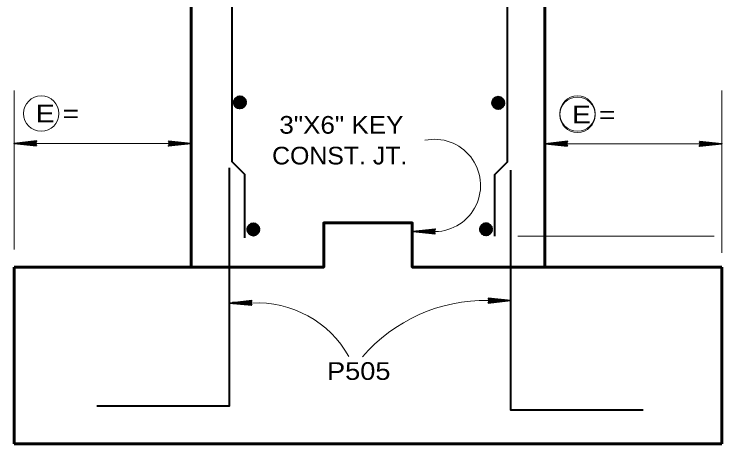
# Model space of a CAD drawing. Extents: x 14.14 to 17.34, y -1.61 to 0.38.
# Drawn here: x 15.5046 to 15.8379, y -1.286 to -1.0834 of the extents above; entities that cross this region are included whole.
import ezdxf

# ---------------------------------------------------------------- set-up
doc = ezdxf.new("R2010")
doc.units = 0
doc.header["$LTSCALE"] = 0.0033
doc.layers.add('1', color=7, linetype='Continuous', lineweight=40)

msp = doc.modelspace()

# ---------------------------------------------------------------- linework, layer by layer
at = {"layer": '1', "lineweight": 13}
for p, q in [((15.504583, -1.194417), (15.504583, -1.119333)), ((15.837917, -1.195917), (15.837917, -1.119333)), ((15.504583, -1.144333), (15.586, -1.144333)), ((15.756167, -1.1445), (15.837917, -1.1445)), ((15.741833, -1.188), (15.83425, -1.188)), ((15.7905, -1.286), (15.8325, -1.286))]:
    msp.add_line(p, q, dxfattribs=at)
at = {"layer": '1'}
for p, q in [((15.60925, -1.123083), (15.613083, -1.12375)), ((15.611167, -1.123917), (15.6125, -1.122917)), ((15.61325, -1.12375), (15.612, -1.122583)), ((15.730917, -1.123333), (15.73475, -1.124)), ((15.732833, -1.124167), (15.734167, -1.123167)), ((15.734917, -1.124), (15.733667, -1.122833)), ((15.608667, -1.126167), (15.6125, -1.126917)), ((15.608667, -1.126333), (15.6125, -1.127083)), ((15.60875, -1.125667), (15.612667, -1.126417)), ((15.60875, -1.125833), (15.612583, -1.126583)), ((15.60875, -1.126083), (15.612583, -1.12675)), ((15.608833, -1.123417), (15.613417, -1.125583)), ((15.608833, -1.12525), (15.61275, -1.126)), ((15.608917, -1.124833), (15.61275, -1.125583)), ((15.608917, -1.125), (15.61275, -1.12575)), ((15.609, -1.124417), (15.612833, -1.125083)), ((15.609, -1.124583), (15.612833, -1.125333)), ((15.609083, -1.123833), (15.613, -1.124583)), ((15.609083, -1.124), (15.613, -1.12475)), ((15.609083, -1.12425), (15.612917, -1.125)), ((15.609167, -1.123417), (15.613083, -1.124083)), ((15.609167, -1.123583), (15.613083, -1.124333)), ((15.613, -1.126583), (15.60925, -1.127)), ((15.730333, -1.126417), (15.734167, -1.127167)), ((15.730333, -1.126583), (15.734167, -1.127333)), ((15.730417, -1.125917), (15.734333, -1.126667)), ((15.730417, -1.126083), (15.73425, -1.126833)), ((15.730417, -1.126333), (15.73425, -1.127)), ((15.7305, -1.123667), (15.735083, -1.125833)), ((15.7305, -1.1255), (15.734417, -1.12625)), ((15.730583, -1.125083), (15.734417, -1.125833)), ((15.730583, -1.12525), (15.734417, -1.126)), ((15.730667, -1.124667), (15.7345, -1.125333)), ((15.730667, -1.124833), (15.7345, -1.125583)), ((15.73075, -1.124083), (15.734667, -1.124833)), ((15.73075, -1.12425), (15.734667, -1.125)), ((15.73075, -1.1245), (15.734583, -1.12525)), ((15.730833, -1.123667), (15.73475, -1.124333)), ((15.730833, -1.123833), (15.73475, -1.124583)), ((15.734667, -1.126833), (15.730917, -1.12725)), ((15.615167, -1.183333), (15.61975, -1.1855)), ((15.6155, -1.183333), (15.619417, -1.184)), ((15.615583, -1.183), (15.619417, -1.183667)), ((15.6175, -1.183833), (15.618833, -1.182833)), ((15.619583, -1.183667), (15.618333, -1.1825)), ((15.72475, -1.18325), (15.729333, -1.185417)), ((15.725083, -1.18325), (15.729, -1.183917)), ((15.725167, -1.182917), (15.729, -1.183583)), ((15.727083, -1.18375), (15.728417, -1.18275)), ((15.729167, -1.183583), (15.727917, -1.182417)), ((15.615, -1.186083), (15.618833, -1.186833)), ((15.615, -1.18625), (15.618833, -1.187)), ((15.615083, -1.185583), (15.619, -1.186333)), ((15.615083, -1.18575), (15.618917, -1.1865)), ((15.615083, -1.186), (15.618917, -1.186667)), ((15.615167, -1.185167), (15.619083, -1.185917)), ((15.61525, -1.18475), (15.619083, -1.1855)), ((15.61525, -1.184917), (15.619083, -1.185667)), ((15.615333, -1.184333), (15.619167, -1.185)), ((15.615333, -1.1845), (15.619167, -1.18525)), ((15.615417, -1.18375), (15.619333, -1.1845)), ((15.615417, -1.183917), (15.619333, -1.184667)), ((15.615417, -1.184167), (15.61925, -1.184917)), ((15.6155, -1.1835), (15.619417, -1.18425)), ((15.619333, -1.1865), (15.615583, -1.186917)), ((15.724583, -1.186), (15.728417, -1.18675)), ((15.724583, -1.186167), (15.728417, -1.186917)), ((15.724667, -1.1855), (15.728583, -1.18625)), ((15.724667, -1.185667), (15.7285, -1.186417)), ((15.724667, -1.185917), (15.7285, -1.186583)), ((15.72475, -1.185083), (15.728667, -1.185833)), ((15.724833, -1.184667), (15.728667, -1.185417)), ((15.724833, -1.184833), (15.728667, -1.185583)), ((15.724917, -1.18425), (15.72875, -1.184917)), ((15.724917, -1.184417), (15.72875, -1.185167)), ((15.725, -1.183667), (15.728917, -1.184417)), ((15.725, -1.183833), (15.728917, -1.184583)), ((15.725, -1.184083), (15.728833, -1.184833)), ((15.725083, -1.183417), (15.729, -1.184167)), ((15.728917, -1.186417), (15.725167, -1.186833))]:
    msp.add_line(p, q, dxfattribs=at)
at = {"layer": '1', "lineweight": 60}
for p, q in [((15.613417, -1.125583), (15.608667, -1.126333)), ((15.609083, -1.123417), (15.608917, -1.126333)), ((15.609333, -1.123417), (15.609083, -1.126333)), ((15.6095, -1.123417), (15.609333, -1.126417)), ((15.609667, -1.123417), (15.609417, -1.126417)), ((15.609833, -1.123417), (15.609667, -1.126417)), ((15.610083, -1.123417), (15.609917, -1.126417)), ((15.610333, -1.123417), (15.610083, -1.126417)), ((15.610417, -1.1235), (15.61025, -1.126417)), ((15.610583, -1.1235), (15.610417, -1.126417)), ((15.61075, -1.1235), (15.610583, -1.126417)), ((15.611, -1.1235), (15.61075, -1.126417)), ((15.611167, -1.1235), (15.611, -1.126417)), ((15.611417, -1.123583), (15.611167, -1.1265)), ((15.611667, -1.123583), (15.611417, -1.1265)), ((15.611833, -1.123583), (15.611667, -1.1265)), ((15.611917, -1.123583), (15.61175, -1.1265)), ((15.612083, -1.123583), (15.611917, -1.1265)), ((15.612167, -1.123583), (15.612, -1.1265)), ((15.612417, -1.123667), (15.612167, -1.126583)), ((15.612583, -1.123667), (15.612417, -1.126583)), ((15.61275, -1.123667), (15.6125, -1.126583)), ((15.612917, -1.123667), (15.61275, -1.126583)), ((15.613167, -1.123667), (15.613, -1.126583)), ((15.613417, -1.125583), (15.61325, -1.12375)), ((15.735083, -1.125833), (15.730333, -1.126583)), ((15.73075, -1.123667), (15.730583, -1.126583)), ((15.731, -1.123667), (15.73075, -1.126583)), ((15.731167, -1.123667), (15.731, -1.126667)), ((15.731333, -1.123667), (15.731083, -1.126667)), ((15.7315, -1.123667), (15.731333, -1.126667)), ((15.73175, -1.123667), (15.731583, -1.126667)), ((15.732, -1.123667), (15.73175, -1.126667)), ((15.732083, -1.12375), (15.731917, -1.126667)), ((15.73225, -1.12375), (15.732083, -1.126667)), ((15.732417, -1.12375), (15.73225, -1.126667)), ((15.732667, -1.12375), (15.732417, -1.126667)), ((15.732833, -1.12375), (15.732667, -1.126667)), ((15.733083, -1.123833), (15.732833, -1.12675)), ((15.733333, -1.123833), (15.733083, -1.12675)), ((15.7335, -1.123833), (15.733333, -1.12675)), ((15.733583, -1.123833), (15.733417, -1.12675)), ((15.73375, -1.123833), (15.733583, -1.12675)), ((15.733833, -1.123833), (15.733667, -1.12675)), ((15.734083, -1.123917), (15.733833, -1.126833)), ((15.73425, -1.123917), (15.734083, -1.126833)), ((15.734417, -1.123917), (15.734167, -1.126833)), ((15.734583, -1.123917), (15.734417, -1.126833)), ((15.734833, -1.123917), (15.734667, -1.126833)), ((15.735083, -1.125833), (15.734917, -1.124)), ((15.615417, -1.183333), (15.61525, -1.18625)), ((15.615667, -1.183333), (15.615417, -1.18625)), ((15.615833, -1.183333), (15.615667, -1.186333)), ((15.616, -1.183333), (15.61575, -1.186333)), ((15.616167, -1.183333), (15.616, -1.186333)), ((15.616417, -1.183333), (15.61625, -1.186333)), ((15.616667, -1.183333), (15.616417, -1.186333)), ((15.725, -1.18325), (15.724833, -1.186167)), ((15.72525, -1.18325), (15.725, -1.186167)), ((15.725417, -1.18325), (15.72525, -1.18625)), ((15.725583, -1.18325), (15.725333, -1.18625)), ((15.72575, -1.18325), (15.725583, -1.18625)), ((15.726, -1.18325), (15.725833, -1.18625)), ((15.72625, -1.18325), (15.726, -1.18625)), ((15.726333, -1.183333), (15.726167, -1.18625)), ((15.7265, -1.183333), (15.726333, -1.18625)), ((15.726667, -1.183333), (15.7265, -1.18625)), ((15.726917, -1.183333), (15.726667, -1.18625)), ((15.727083, -1.183333), (15.726917, -1.18625)), ((15.61975, -1.1855), (15.615, -1.18625)), ((15.61675, -1.183417), (15.616583, -1.186333)), ((15.616917, -1.183417), (15.61675, -1.186333)), ((15.617083, -1.183417), (15.616917, -1.186333)), ((15.617333, -1.183417), (15.617083, -1.186333)), ((15.6175, -1.183417), (15.617333, -1.186333)), ((15.61775, -1.1835), (15.6175, -1.186417)), ((15.618, -1.1835), (15.61775, -1.186417)), ((15.618167, -1.1835), (15.618, -1.186417)), ((15.61825, -1.1835), (15.618083, -1.186417)), ((15.618417, -1.1835), (15.61825, -1.186417)), ((15.6185, -1.1835), (15.618333, -1.186417)), ((15.61875, -1.183583), (15.6185, -1.1865)), ((15.618917, -1.183583), (15.61875, -1.1865)), ((15.619083, -1.183583), (15.618833, -1.1865)), ((15.61925, -1.183583), (15.619083, -1.1865)), ((15.6195, -1.183583), (15.619333, -1.1865)), ((15.61975, -1.1855), (15.619583, -1.183667)), ((15.729333, -1.185417), (15.724583, -1.186167)), ((15.727333, -1.183417), (15.727083, -1.186333)), ((15.727583, -1.183417), (15.727333, -1.186333)), ((15.72775, -1.183417), (15.727583, -1.186333)), ((15.727833, -1.183417), (15.727667, -1.186333)), ((15.728, -1.183417), (15.727833, -1.186333)), ((15.728083, -1.183417), (15.727917, -1.186333)), ((15.728333, -1.1835), (15.728083, -1.186417)), ((15.7285, -1.1835), (15.728333, -1.186417)), ((15.728667, -1.1835), (15.728417, -1.186417)), ((15.728833, -1.1835), (15.728667, -1.186417)), ((15.729083, -1.1835), (15.728917, -1.186417)), ((15.729333, -1.185417), (15.729167, -1.183583)), ((15.504583, -1.286), (15.504583, -1.202667)), ((15.837917, -1.202667), (15.837917, -1.286)), ((15.837917, -1.286), (15.504583, -1.286))]:
    msp.add_line(p, q, dxfattribs=at)
at = {"layer": '1', "lineweight": 35}
for p, q in [((15.514917, -1.14325), (15.507583, -1.144083)), ((15.5775, -1.143333), (15.585333, -1.14425)), ((15.5775, -1.143333), (15.585333, -1.14425)), ((15.515167, -1.144333), (15.504583, -1.144333)), ((15.514917, -1.145167), (15.507083, -1.144167)), ((15.514917, -1.145167), (15.507083, -1.144333)), ((15.514917, -1.145333), (15.507083, -1.144417)), ((15.514917, -1.145333), (15.507083, -1.144417)), ((15.514917, -1.14525), (15.507083, -1.144417)), ((15.514917, -1.143417), (15.507583, -1.144167)), ((15.514917, -1.1435), (15.507583, -1.144333)), ((15.515, -1.143667), (15.507667, -1.144417)), ((15.57725, -1.144333), (15.587833, -1.144333)), ((15.577417, -1.145), (15.58475, -1.14425)), ((15.5775, -1.143417), (15.585333, -1.14425)), ((15.5775, -1.1435), (15.585333, -1.144333)), ((15.5775, -1.1435), (15.585333, -1.1445)), ((15.5775, -1.145167), (15.584833, -1.144333)), ((15.5775, -1.14525), (15.584833, -1.1445)), ((15.5775, -1.145417), (15.584833, -1.144583)), ((15.76525, -1.1445), (15.754667, -1.1445)), ((15.765, -1.145333), (15.757167, -1.144333)), ((15.765, -1.145333), (15.757167, -1.1445)), ((15.765, -1.1455), (15.757167, -1.144583)), ((15.765, -1.1455), (15.757167, -1.144583)), ((15.765, -1.145417), (15.757167, -1.144583)), ((15.765, -1.143417), (15.757667, -1.14425)), ((15.765, -1.143583), (15.757667, -1.144333)), ((15.765, -1.143667), (15.757667, -1.1445)), ((15.765083, -1.143833), (15.75775, -1.144583)), ((15.827333, -1.1445), (15.837917, -1.1445)), ((15.8275, -1.145167), (15.834833, -1.144417)), ((15.827583, -1.1435), (15.835417, -1.144417)), ((15.827583, -1.1435), (15.835417, -1.144417)), ((15.827583, -1.143583), (15.835417, -1.144417)), ((15.827583, -1.143667), (15.835417, -1.1445)), ((15.827583, -1.143667), (15.835417, -1.144667)), ((15.827583, -1.145333), (15.834917, -1.1445)), ((15.827583, -1.145417), (15.834917, -1.144667)), ((15.827583, -1.145583), (15.834917, -1.14475)), ((15.702917, -1.185917), (15.692333, -1.185917)), ((15.702667, -1.18675), (15.694833, -1.18575)), ((15.702667, -1.18675), (15.694833, -1.185917)), ((15.702667, -1.186917), (15.694833, -1.186)), ((15.702667, -1.186917), (15.694833, -1.186)), ((15.702667, -1.186833), (15.694833, -1.186)), ((15.702667, -1.184833), (15.695333, -1.185667)), ((15.702667, -1.185), (15.695333, -1.18575)), ((15.702667, -1.185083), (15.695333, -1.185917)), ((15.70275, -1.18525), (15.695417, -1.186)), ((15.6165, -1.219583), (15.605917, -1.219583)), ((15.61625, -1.220417), (15.608417, -1.219417)), ((15.61625, -1.220417), (15.608417, -1.219583)), ((15.61625, -1.220583), (15.608417, -1.219667)), ((15.61625, -1.220583), (15.608417, -1.219667)), ((15.61625, -1.2205), (15.608417, -1.219667)), ((15.61625, -1.2185), (15.608917, -1.219333)), ((15.61625, -1.218667), (15.608917, -1.219417)), ((15.61625, -1.21875), (15.608917, -1.219583)), ((15.616333, -1.218917), (15.609, -1.219667)), ((15.727917, -1.218417), (15.7385, -1.218417)), ((15.728083, -1.219083), (15.735417, -1.218333)), ((15.728167, -1.217417), (15.736, -1.218333)), ((15.728167, -1.217417), (15.736, -1.218333)), ((15.728167, -1.2175), (15.736, -1.218333)), ((15.728167, -1.217583), (15.736, -1.218417)), ((15.728167, -1.217583), (15.736, -1.218583)), ((15.728167, -1.21925), (15.7355, -1.218417)), ((15.728167, -1.219333), (15.7355, -1.218583)), ((15.728167, -1.2195), (15.7355, -1.218667))]:
    msp.add_line(p, q, dxfattribs=at)
at = {"layer": '1', "lineweight": 60}
for points in [[(15.504583, -1.202667), (15.587917, -1.202667), (15.587917, -0.869333), (15.754583, -0.869333), (15.754583, -1.202667), (15.837917, -1.202667)], [(15.6125, -1.127083), (15.6125, -1.122917), (15.610833, -1.127583), (15.611333, -1.122417), (15.60925, -1.127), (15.61, -1.1225), (15.611583, -1.1275), (15.608417, -1.124167), (15.61325, -1.12375), (15.61, -1.127417), (15.612, -1.122583), (15.608833, -1.123417), (15.608667, -1.126333)], [(15.60925, -1.127), (15.61075, -1.12475), (15.608583, -1.123833), (15.610583, -1.122417), (15.61075, -1.124667), (15.612417, -1.127), (15.608417, -1.124667), (15.611167, -1.123917)], [(15.612, -1.122583), (15.61075, -1.12475), (15.613, -1.126583)], [(15.734167, -1.127333), (15.734167, -1.123167), (15.7325, -1.127833), (15.733, -1.122667), (15.730917, -1.12725), (15.731667, -1.12275), (15.73325, -1.12775), (15.730083, -1.124417), (15.734917, -1.124), (15.731667, -1.127667), (15.733667, -1.122833), (15.7305, -1.123667), (15.730333, -1.126583)], [(15.730917, -1.12725), (15.732417, -1.125), (15.73025, -1.124083), (15.73225, -1.122667), (15.732417, -1.124917), (15.734083, -1.12725), (15.730083, -1.124917), (15.732833, -1.124167)], [(15.733667, -1.122833), (15.732417, -1.125), (15.734667, -1.126833)], [(15.60825, -1.125083), (15.613417, -1.124417), (15.608833, -1.123417)], [(15.729917, -1.125333), (15.735083, -1.124667), (15.7305, -1.123667)], [(15.587917, -1.202667), (15.650417, -1.202667), (15.650417, -1.181833), (15.692083, -1.181833), (15.692083, -1.202667), (15.754583, -1.202667)], [(15.614583, -1.185), (15.61975, -1.184333), (15.615167, -1.183333)], [(15.618833, -1.187), (15.618833, -1.182833), (15.617167, -1.1875), (15.617667, -1.182333), (15.615583, -1.186917), (15.616333, -1.182417), (15.617917, -1.187417), (15.61475, -1.184083), (15.619583, -1.183667), (15.616333, -1.187333), (15.618333, -1.1825), (15.615167, -1.183333), (15.615, -1.18625)], [(15.615583, -1.186917), (15.617083, -1.184667), (15.614917, -1.18375), (15.616917, -1.182333), (15.617083, -1.184583), (15.61875, -1.186917), (15.61475, -1.184583), (15.6175, -1.183833)], [(15.618333, -1.1825), (15.617083, -1.184667), (15.619333, -1.1865)], [(15.724167, -1.184917), (15.729333, -1.18425), (15.72475, -1.18325)], [(15.728417, -1.186917), (15.728417, -1.18275), (15.72675, -1.187417), (15.72725, -1.18225), (15.725167, -1.186833), (15.725917, -1.182333), (15.7275, -1.187333), (15.724333, -1.184), (15.729167, -1.183583), (15.725917, -1.18725), (15.727917, -1.182417), (15.72475, -1.18325), (15.724583, -1.186167)], [(15.725167, -1.186833), (15.726667, -1.184583), (15.7245, -1.183667), (15.7265, -1.18225), (15.726667, -1.1845), (15.728333, -1.186833), (15.724333, -1.1845), (15.727083, -1.18375)], [(15.727917, -1.182417), (15.726667, -1.184583), (15.728917, -1.186417)]]:
    msp.add_lwpolyline(points, dxfattribs=at)
at = {"layer": '1'}
for points in [[(15.613083, -0.89), (15.613083, -0.938667), (15.607167, -0.944583), (15.607167, -1.152917), (15.613083, -1.158833), (15.613083, -1.188833)], [(15.731, -1.188), (15.731, -1.158917), (15.736917, -1.153), (15.736917, -0.944667), (15.731, -0.93875), (15.731, -0.890167)], [(15.608667, -1.126333), (15.61075, -1.127583), (15.6125, -1.127083), (15.613417, -1.125583)], [(15.730333, -1.126583), (15.732417, -1.127833), (15.734167, -1.127333), (15.735083, -1.125833)], [(15.5435, -1.268083), (15.606, -1.268083), (15.606, -1.155917)], [(15.738333, -1.156917), (15.738333, -1.269917), (15.800833, -1.269917)], [(15.615, -1.18625), (15.617083, -1.1875), (15.618833, -1.187), (15.61975, -1.1855)], [(15.724583, -1.186167), (15.726667, -1.187417), (15.728417, -1.186917), (15.729333, -1.185417)]]:
    msp.add_lwpolyline(points, dxfattribs=at)
at = {"layer": '1', "lineweight": 35}
for points in [[(15.515167, -1.145417), (15.504583, -1.144333), (15.515167, -1.143167), (15.514583, -1.144333)], [(15.57725, -1.14325), (15.587833, -1.144333), (15.57725, -1.1455), (15.577833, -1.144333)], [(15.76525, -1.145583), (15.754667, -1.1445), (15.76525, -1.143333), (15.764667, -1.1445)], [(15.514417, -1.144417), (15.50975, -1.1445), (15.50975, -1.144417), (15.510667, -1.144417), (15.514417, -1.1445), (15.511417, -1.144583), (15.514583, -1.144667), (15.512333, -1.14475), (15.514583, -1.144833), (15.511083, -1.144583), (15.506417, -1.144417), (15.507333, -1.144167), (15.506083, -1.144167), (15.514417, -1.144167), (15.512, -1.144), (15.514583, -1.144), (15.50925, -1.144417), (15.514583, -1.14375)], [(15.578, -1.14425), (15.582667, -1.144167), (15.582667, -1.14425), (15.58175, -1.14425), (15.578, -1.144167), (15.581, -1.144083), (15.577833, -1.144), (15.580083, -1.143917), (15.577833, -1.143833), (15.581333, -1.144083), (15.586, -1.14425), (15.585083, -1.1445), (15.586333, -1.1445), (15.578, -1.1445), (15.580417, -1.144667), (15.577833, -1.144667), (15.583167, -1.14425), (15.577833, -1.144917)], [(15.7645, -1.144583), (15.759833, -1.144667), (15.759833, -1.144583), (15.76075, -1.144583), (15.7645, -1.144667), (15.7615, -1.14475), (15.764667, -1.144833), (15.762417, -1.144917), (15.764667, -1.145), (15.761167, -1.14475), (15.7565, -1.144583), (15.757417, -1.144333), (15.756167, -1.144333), (15.7645, -1.144333), (15.762083, -1.144167), (15.764667, -1.144167), (15.759333, -1.144583), (15.764667, -1.143917)], [(15.827333, -1.143417), (15.837917, -1.1445), (15.827333, -1.145667), (15.827917, -1.1445)], [(15.828083, -1.144417), (15.83275, -1.144333), (15.83275, -1.144417), (15.831833, -1.144417), (15.828083, -1.144333), (15.831083, -1.14425), (15.827917, -1.144167), (15.830167, -1.144083), (15.827917, -1.144), (15.831417, -1.14425), (15.836083, -1.144417), (15.835167, -1.144667), (15.836417, -1.144667), (15.828083, -1.144667), (15.8305, -1.144833), (15.827917, -1.144833), (15.83325, -1.144417), (15.827917, -1.145083)], [(15.702917, -1.187), (15.692333, -1.185917), (15.702917, -1.18475), (15.702333, -1.185917)], [(15.702167, -1.186), (15.6975, -1.186083), (15.6975, -1.186), (15.698417, -1.186), (15.702167, -1.186083), (15.699167, -1.186167), (15.702333, -1.18625), (15.700083, -1.186333), (15.702333, -1.186417), (15.698833, -1.186167), (15.694167, -1.186), (15.695083, -1.18575), (15.693833, -1.18575), (15.702167, -1.18575), (15.69975, -1.185583), (15.702333, -1.185583), (15.697, -1.186), (15.702333, -1.185333)], [(15.6165, -1.220667), (15.605917, -1.219583), (15.6165, -1.218417), (15.615917, -1.219583)], [(15.61575, -1.219667), (15.611083, -1.21975), (15.611083, -1.219667), (15.612, -1.219667), (15.61575, -1.21975), (15.61275, -1.219833), (15.615917, -1.219917), (15.613667, -1.22), (15.615917, -1.220083), (15.612417, -1.219833), (15.60775, -1.219667), (15.608667, -1.219417), (15.607417, -1.219417), (15.61575, -1.219417), (15.613333, -1.21925), (15.615917, -1.21925), (15.610583, -1.219667), (15.615917, -1.219)], [(15.727917, -1.217333), (15.7385, -1.218417), (15.727917, -1.219583), (15.7285, -1.218417)], [(15.728667, -1.218333), (15.733333, -1.21825), (15.733333, -1.218333), (15.732417, -1.218333), (15.728667, -1.21825), (15.731667, -1.218167), (15.7285, -1.218083), (15.73075, -1.218), (15.7285, -1.217917), (15.732, -1.218167), (15.736667, -1.218333), (15.73575, -1.218583), (15.737, -1.218583), (15.728667, -1.218583), (15.731083, -1.21875), (15.7285, -1.21875), (15.733833, -1.218333), (15.7285, -1.219)]]:
    msp.add_lwpolyline(points, close=True, dxfattribs=at)
for points in [[(15.514417, -1.144417), (15.514833, -1.145167), (15.514583, -1.144917), (15.514417, -1.144583), (15.514167, -1.144667), (15.514333, -1.145), (15.5145, -1.14425), (15.514667, -1.14375), (15.514917, -1.143333)], [(15.578, -1.14425), (15.577583, -1.1435), (15.577833, -1.14375), (15.578, -1.144083), (15.57825, -1.144), (15.578083, -1.143667), (15.577917, -1.144417), (15.57775, -1.144917), (15.5775, -1.145333)], [(15.7645, -1.144583), (15.764917, -1.145333), (15.764667, -1.145083), (15.7645, -1.14475), (15.76425, -1.144833), (15.764417, -1.145167), (15.764583, -1.144417), (15.76475, -1.143917), (15.765, -1.1435)], [(15.828083, -1.144417), (15.827667, -1.143667), (15.827917, -1.143917), (15.828083, -1.14425), (15.828333, -1.144167), (15.828167, -1.143833), (15.828, -1.144583), (15.827833, -1.145083), (15.827583, -1.1455)], [(15.702167, -1.186), (15.702583, -1.18675), (15.702333, -1.1865), (15.702167, -1.186167), (15.701917, -1.18625), (15.702083, -1.186583), (15.70225, -1.185833), (15.702417, -1.185333), (15.702667, -1.184917)], [(15.61575, -1.219667), (15.616167, -1.220417), (15.615917, -1.220167), (15.61575, -1.219833), (15.6155, -1.219917), (15.615667, -1.22025), (15.615833, -1.2195), (15.616, -1.219), (15.61625, -1.218583)], [(15.728667, -1.218333), (15.72825, -1.217583), (15.7285, -1.217833), (15.728667, -1.218167), (15.728917, -1.218083), (15.72875, -1.21775), (15.728583, -1.2185), (15.728417, -1.219), (15.728167, -1.219417)]]:
    msp.add_lwpolyline(points, dxfattribs=at)
at = {"layer": '1', "lineweight": 13}
for centre in [(15.517333, -1.13025), (15.769917, -1.13025), (15.769917, -1.130833)]:
    msp.add_circle(centre, 0.008333, dxfattribs=at)
at = {"layer": '1', "lineweight": 60}
for centre in [(15.610917, -1.124983), (15.732583, -1.125233), (15.61725, -1.1849), (15.726833, -1.184817)]:
    msp.add_circle(centre, 0.00264, dxfattribs=at)
at = {"layer": '1', "lineweight": 13}
for centre, radius, start, end in [((15.702495, -1.164151), 0.02177, 271.10937, 101.69263), ((15.618951, -1.269296), 0.049773, 29.5481, 92.8223), ((15.726511, -1.294605), 0.076202, 88.94317, 139.38493)]:
    msp.add_arc(centre, radius, start, end, dxfattribs=at)

# ---------------------------------------------------------------- texts
at = {"layer": '1'}
for s, height, width, p in [('E =      ', 0.008334, 1.2, (15.51475, -1.134417)), ('E =      ', 0.008334, 1.2, (15.767333, -1.134917)), ('3"X6" KEY', 0.008334, 1.1, (15.6295, -1.13975)), ('CONST. JT. ', 0.008334, 1.05, (15.626083, -1.15425)), ('P505', 0.008333, 1.15, (15.651917, -1.255833))]:
    msp.add_text(s, height=height, dxfattribs=dict(at, width=width)).set_placement(p)

doc.saveas('drawing.dxf')
